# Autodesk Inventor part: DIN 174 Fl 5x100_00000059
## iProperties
Created: 2006-03
Part Number: DIN 174 Fl 5x100_00000059
Material: Default
Document SubType Name: Modeling
Designer: Carlo
Stock Number: DIN 174 Fl 5x100
Mass: 773.849 g
Surface Area: 3260.58 cm^2
Volume: 773.849 cm^3
Density: 1 g/cm^3
G_L: 1547.896 mm
G_W: 5.000 mm
G_H: 100.000 mm
AFG_Item: 100 x 5
CSToolsMass: 1.0
CSToolsVolume: 773849.0
CSToolsArea: 3261.0
Author: Carlo
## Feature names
1. AFG_Detailed_DIN 174 Fl 5x100_00000059 [Extrusion]
2. AFG_Simplified_DIN 174 Fl 5x100_00000059 [Extrusion]
3. AFG_StartExtrusion_1 [Extrusion]
4. AFG_StartExtrusion_2 [Extrusion]
5. AFG_EndExtrusion_1 [Extrusion]
6. AFG_EndExtrusion_2 [Extrusion]
